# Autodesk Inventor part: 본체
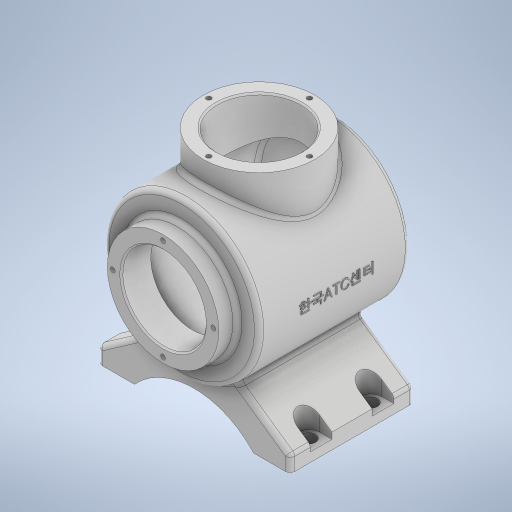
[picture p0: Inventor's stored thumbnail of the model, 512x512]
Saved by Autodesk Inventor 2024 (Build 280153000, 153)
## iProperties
Created: 2023-08
Part Number: 본체
Material: 일반
Document SubType Name: Modeling
Designer: Owner
Density: 1 g/cm^3
Appearance: 기본값
Author: Owner
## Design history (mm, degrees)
sketch "스케치1"
  geometry: L1 (0, 60)-(0, -60); L2 (0, 60)-(36, 60); L3 (36, 60)-(36, 48); L4 (36, 48)-(50, 48); L5 (50, 48)-(50, -48.336); L6 (27, 60)-(27, 41); L7 (27, 41)-(43, 41); L8 (43, 41)-(43, -43.887); A1 r 113 centre (0, 53) between (0, -60) and (50, -48.336); A2 r 106 centre (0, 53) between (0, -53) and (43, -43.887); 2 further points
  constraints: 16 end point, 6 perpendicular, 4 point on circle, 3 point on line, 2 centre point, 1 coincident, 1 horizontal, 1 midpoint, 1 vertical
  dimensions: "d0" = 120 distance of L1.start L1.end; "d1" = 72 diameter of L3 L1; "d2" = 100 diameter of L5 L1; "d3" = 113 radius of A1; "d5" = 108 distance from line of L1.end L4; "d6" = 7 radial gap between concentric circles of A1 A2; "d7" = 54 diameter of L6 L1; "d8" = 86 diameter of L8 L1; "d9" = 19 distance of L6.start L6.end
revolve "회전1" sketch "스케치1" stored, may be unused: angle "d10" = 90 deg
node "작업 평면1"
sketch "스케치2"
  geometry: L1 (62, -40)-(-62, -40); L2 (-62, -40)-(-62, 40); L3 (-62, 40)-(62, 40); L4 (62, 40)-(62, -40); L5 (62, -40)-(-62, 40); L6 (-62, -40)-(62, 40); 2 further points
  constraints: 12 end point, 2 midpoint, 2 parallel, 1 coincident, 1 horizontal, 1 perpendicular
  dimensions: "d17" = 124 distance of L2.end L3.end; "d18" = 80 distance of L1.end L2.end
extrude "돌출1" join sketch "스케치2" distance "d19" = 10; taper "d20" = 0 deg
sketch "스케치3"
  geometry: L1 (-62, -40)-(62, -40) reference; L2 (-14.332, 40)-(14.332, 40); L3 (14.332, 40)-(14.332, -40); L4 (14.332, -40)-(-14.332, -40); L5 (-14.332, -40)-(-14.332, 40); L6 (-14.332, 40)-(14.332, -40); L7 (14.332, 40)-(-14.332, -40); 3 further points
  constraints: 12 end point, 2 midpoint, 2 parallel, 1 coincident, 1 horizontal, 1 perpendicular, 1 point on line
  dimensions: "d21" = 28.66375 distance of L2.start L2.end
extrude "돌출2" join sketch "스케치3" stored distance "d22" = 10; taper "d23" = 0 deg
sketch "스케치4"
  geometry: L1 (62, -67)-(38.713, -50.694); L2 (62, -77)-(62, -67) reference; 1 further point
  constraints: 2 end point, 1 coincident
  dimensions: "d24" = 55 deg angle of L2 L1
feature "리브1" sketch "스케치4" dims "d25" = 1, "d26" = 80, "d27" = 0, "d28" = 0, "d29" = 1, "d30" = 1
node "작업 평면2"
sketch "스케치6"
  geometry: L1 (62, -40)-(-62, -40) reference; L2 (62, 40)-(62, -40) reference; L3 (54, -27)-(62, -27); L4 (54, -13)-(62, -13); A1 r 7 centre (54, -20) between (54, -13) and (54, -27); 1 further point
  constraints: 4 end point, 2 perpendicular, 2 point on circle, 2 point on line, 2 tangent, 1 centre point
  dimensions: "d32" = 14 diameter of A1; "d33" = 20 distance from line of A1.centre L1; "d34" = 8 distance from line of L2 A1.centre
extrude "돌출3" cut sketch "스케치6" stored distance "d35" = 0; taper "d36" = 0 deg
sketch "스케치7"
  geometry: A1 r 7 centre (54, 20) between (54, 27) and (54, 13) reference; 2 further points
  constraints: 1 coincident
hole "구멍1" sketch "스케치7" at (54, 20) diameter "d37" = 9; stored, may be unused: countersink angle "d41" = 90 deg, drill point angle "d43" = 118 deg; dims "d38" = 8, "d39" = 4, "d40" = 2, "d42" = 10
sketch "스케치8"
  geometry: L1 (0, 0)-(124, 0) reference; A1 r 52.096 centre (62, -35.096) between (100.5, 0) and (23.5, 0); 2 further points
  constraints: 3 point on circle, 2 point on line, 1 centre point, 1 vertical alignment
  dimensions: "d44" = 77 distance of A1.start A1.end; "d45" = 17 distance from line of L1 point (62, 17)
extrude "돌출4" cut sketch "스케치8" extent not by distance; stored distance "d46" = 10; taper "d47" = 0 deg
node "작업 평면3"
sketch "스케치9"
  geometry: L1 (-36, 60)-(36, 60) reference; C1 r 36 at (0, -2); 1 further point
  constraints: 1 centre point, 1 vertical alignment
  dimensions: "d49" = 72 diameter of C1; "d50" = 62 distance from line of C1.centre L1
extrude "돌출5" join sketch "스케치9" stored distance "d51" = 10; taper "d52" = 0 deg
sketch "스케치10"
  geometry: C1 r 36 at (0, 0) reference; C2 r 27 at (0, 0); 1 further point
  constraints: 1 centre point, 1 coincident
  dimensions: "d53" = 54 diameter of C2
extrude "돌출6" cut sketch "스케치10" stored distance "d54" = 10; taper "d55" = 0 deg
sketch "스케치11"
  geometry: C1 r 27 at (0, 0) reference; 2 further points
  constraints: 1 vertical alignment
  dimensions: "d56" = 32.5 distance of C1.centre point (0, 32.5)
hole "구멍2" sketch "스케치11" at (0, 32.5) diameter "d57" = 3.242; stored, may be unused: countersink angle "d61" = 90 deg, drill point angle "d63" = 118 deg; dims "d58" = 8, "d59" = 4, "d60" = 2, "d62" = 10
sketch "스케치12"
  geometry: 2 further points
  constraints: 1 vertical alignment
  dimensions: "d67" = 32.5 distance of point (0, 0) point (0, 32.5)
hole "구멍3" sketch "스케치12" at (0, 32.5) diameter "d68" = 3.242; stored, may be unused: countersink angle "d72" = 90 deg, drill point angle "d74" = 118 deg; dims "d69" = 8, "d70" = 4, "d71" = 2, "d73" = 10
fillet "모깎기1" dims "d78" = 3
fillet "모깎기2" dims "d79" = 3
fillet "모깎기3" dims "d80" = 3
fillet "모깎기4" dims "d81" = 3
chamfer "모따기1" distance "d82" = 1; stored, may be unused: second distance "d83" = 2, angle "d84" = 45 deg
node "작업 평면4"
sketch "스케치13"
  geometry: L1 (-36, 60.168)-(36, 60.168) reference; 2 further points
  constraints: 1 vertical alignment, 1 other
  dimensions: "d85" = 62 distance from line of point (0, -1.832) L1
feature "엠보싱1" sketch "스케치13" dims "d0" = 120, "d1" = 72, "d2" = 100, "d3" = 113, "d5" = 108, "d6" = 7, "d7" = 54, "d8" = 86, "d9" = 19, "d86" = 0.5, "d87" = 0
feature "ͦ耀ͨ耀ͪ耀ͬ耀ͮ耀Ͱ耀Ͳ耀ʹ耀" dims "d0" = 120, "d1" = 72, "d2" = 100, "d3" = 113, "d5" = 108, "d6" = 7, "d7" = 54, "d8" = 86, "d9" = 19, "d10" = 90 deg, "d11" = -77, "d17" = 124, "d18" = 80, "d19" = 10, "d20" = 0, "d21" = 28.66375, "d22" = 10, "d23" = 0, "d24" = 55 deg, "d25" = 1, "d26" = 80, "d27" = 0, "d28" = 0, "d29" = 1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
node "솔리드1"
mirror "미러1"
mirror "미러2"
mirror "미러3"
pattern_circular "원형 패턴1" dims angle "d65" = 360 deg
pattern_circular "원형 패턴2" dims angle "d76" = 360 deg
feature "A9D066F2-1C7D-4E18-AEED-F7BC21143FA4" dims "d37" = 9, "d38" = 8, "d39" = 4, "d40" = 2, "d41" = 90 deg, "d42" = 10, "d43" = 118 deg
